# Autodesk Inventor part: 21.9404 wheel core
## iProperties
Created: 2010-10
Part Number: 21.9404 wheel core
Document SubType Name: Modeling
Designer: Administrator
Density: 1.4 g/cm^3
Material: PVC-U
Mass: 169.728 g
Surface Area: 314.85 cm^2
Volume: 121.234 cm^3
Author: Administrator
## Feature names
1. Base1
